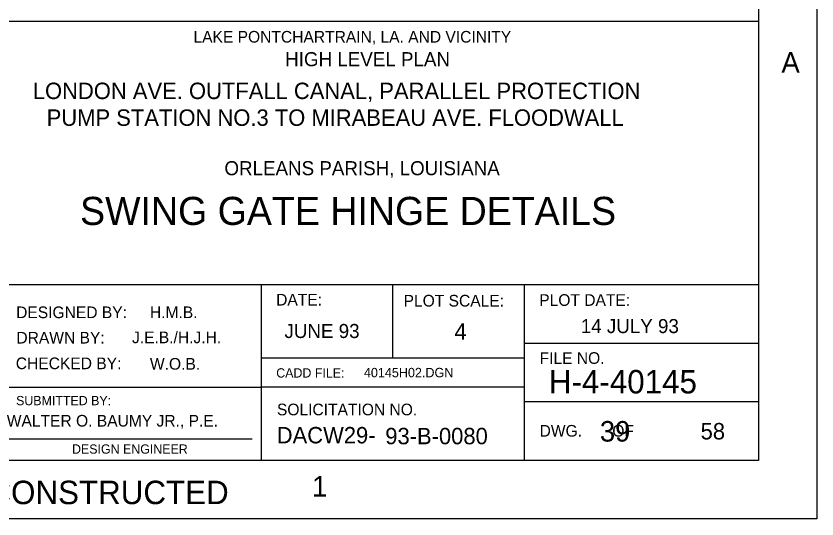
# Model space of a CAD drawing. Extents: x -0.2 to 13.5, y -0.2 to 9.5.
# Drawn here: x 11.051 to 13.333, y 0 to 1.432 of the extents above; entities that cross this region are included whole.
import ezdxf

# ---------------------------------------------------------------- set-up
doc = ezdxf.new("R2010")
doc.units = 0
doc.layers.add('Level 1', color=7, linetype='Continuous')
doc.layers.add('Level 2', color=7, linetype='Continuous')

msp = doc.modelspace()

# ---------------------------------------------------------------- linework, layer by layer
at = {"layer": 'Level 1'}
for p, q in [((13.1667, 1.4167), (11, 1.4167)), ((13.1667, 0.6667), (11, 0.6667)), ((11.75, 0.1667), (11.75, 0.6667)), ((12.125, 0.4583), (12.125, 0.6667)), ((12.5, 0.1667), (12.5, 0.6667)), ((13.1667, 0.5), (12.5, 0.5)), ((12.5, 0.4583), (11.75, 0.4583)), ((11, 0.375), (11.75, 0.375)), ((12.5, 0.375), (11.75, 0.375)), ((13.1667, 0.3333), (12.5, 0.3333)), ((11.0224, 0.2278), (11.7234, 0.2278))]:
    msp.add_line(p, q, dxfattribs=at)
for points in [[(0, 9.3333), (13.3333, 9.3333), (13.3333, 0), (0, 0)], [(0.5, 9.1667), (13.1667, 9.1667), (13.1667, 0.1667), (0.5, 0.1667)]]:
    msp.add_lwpolyline(points, close=True, dxfattribs=at)

# ---------------------------------------------------------------- texts
for s, height, p in [('A', 0.0584, (13.2321, 1.2711)), ('DATE:', 0.03321, (11.792, 0.6079)), ('PLOT DATE:', 0.03321, (12.5418, 0.6069)), ('PLOT SCALE:', 0.033208, (12.1552, 0.605)), ('DESIGNED BY:', 0.033208, (11.051, 0.5719)), ('DRAWN BY:', 0.03321, (11.0517, 0.4997)), ('CHECKED BY:', 0.033208, (11.05, 0.4266)), ('FILE NO.', 0.03321, (12.5428, 0.4417)), ('CADD FILE:', 0.02642, (11.7923, 0.4028)), ('SUBMITTED BY:', 0.026417, (11.0508, 0.3239)), ('SOLICITATION NO.', 0.033208, (11.7943, 0.2952)), ('DACW29-', 0.04679, (11.7937, 0.2152)), ('DWG.       OF', 0.033208, (12.5428, 0.2345)), ('DESIGN ENGINEER', 0.026417, (11.2103, 0.1859)), ('1', 0.0584, (11.8942, 0.0637))]:
    msp.add_text(s, height=height, dxfattribs=at).set_placement(p)
at = {"layer": 'Level 2'}
for s, height, p in [('LAKE PONTCHARTRAIN, LA. AND VICINITY', 0.033208, (11.5564, 1.3566)), ('HIGH LEVEL PLAN', 0.04, (11.8178, 1.2894)), ('LONDON AVE. OUTFALL CANAL, PARALLEL PROTECTION', 0.046792, (11.0985, 1.1958)), ('PUMP STATION NO.3 TO MIRABEAU AVE. FLOODWALL', 0.046792, (11.1381, 1.1196)), ('ORLEANS PARISH, LOUISIANA', 0.04, (11.6446, 0.979)), ('SWING GATE HINGE DETAILS', 0.079999, (11.2332, 0.8373)), ('H.M.B.', 0.03321, (11.4323, 0.572)), ('JUNE 93', 0.04, (11.8157, 0.5153)), ('4', 0.0468, (12.3, 0.5104)), ('14 JULY 93', 0.04, (12.6602, 0.5293)), ('J.E.B./H.J.H.', 0.033208, (11.3812, 0.5006)), ('W.O.B.', 0.03321, (11.4323, 0.4252)), ('40145H02.DGN', 0.026792, (12.0421, 0.4035)), ('H-4-40145', 0.06679, (12.5692, 0.3575)), ('WALTER O. BAUMY JR., P.E.', 0.033208, (11.0243, 0.2631)), ('39', 0.05842, (12.7146, 0.2204)), ('58', 0.04679, (13.0017, 0.2265)), ('93-B-0080', 0.04679, (12.103, 0.2127)), ('AS CONSTRUCTED', 0.066792, (10.8281, 0.0422))]:
    msp.add_text(s, height=height, dxfattribs=at).set_placement(p)

doc.saveas('drawing.dxf')
